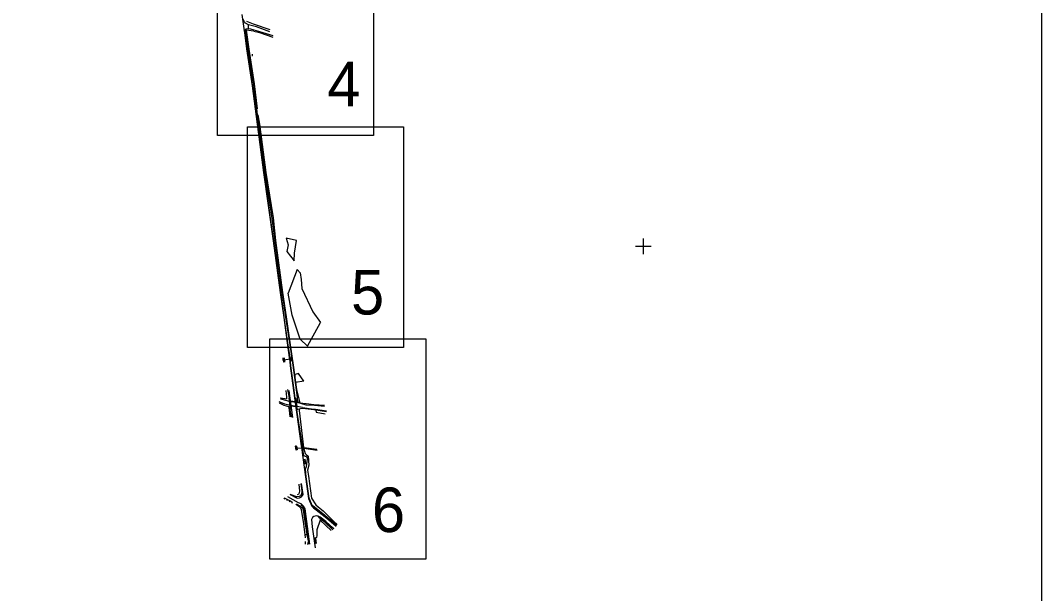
# Model space of a CAD drawing. Extents: x -866693 to -866303, y -1041966 to -1040244.
# Drawn here: x -866441.9 to -866373.2, y -1041273.4 to -1041234.8 of the extents above; entities that cross this region are included whole.
import ezdxf

# ---------------------------------------------------------------- set-up
doc = ezdxf.new("R2010")
doc.units = 0
for name, color, linetype in [('Formát', 7, 'Continuous'), ('Legenda', 7, 'Continuous'), ('Síť křížek', 7, 'Continuous')]:
    doc.layers.add(name, color=color, linetype=linetype)

msp = doc.modelspace()

# ---------------------------------------------------------------- linework, layer by layer
at = {"layer": 'Formát'}
msp.add_lwpolyline([(-866583.195, -1041098.65), (-866373.195, -1041098.65), (-866373.195, -1041395.65), (-866583.195, -1041395.65)], close=True, dxfattribs=at)
at = {"layer": 'Legenda'}
for p, q in [((-866426.854, -1041234.885), (-866426.936, -1041234.732)), ((-866426.787, -1041234.977), (-866426.854, -1041234.885)), ((-866426.587, -1041235.082), (-866426.787, -1041234.977)), ((-866426.248, -1041235.044), (-866426.69, -1041234.857)), ((-866426.59, -1041235.342), (-866426.587, -1041235.082)), ((-866426.042, -1041235.237), (-866426.587, -1041235.082)), ((-866425.13, -1041235.427), (-866426.248, -1041235.044)), ((-866425.153, -1041235.557), (-866426.042, -1041235.237)), ((-866426.866, -1041235.487), (-866426.844, -1041235.454)), ((-866426.844, -1041235.454), (-866426.731, -1041235.361)), ((-866426.844, -1041235.454), (-866426.742, -1041235.444)), ((-866426.806, -1041235.451), (-866426.844, -1041235.454)), ((-866426.682, -1041236.715), (-866426.844, -1041235.454)), ((-866426.742, -1041235.444), (-866426.806, -1041235.451)), ((-866426.806, -1041235.451), (-866426.618, -1041236.723)), ((-866426.225, -1041235.528), (-866426.742, -1041235.444)), ((-866426.742, -1041235.444), (-866426.553, -1041236.737)), ((-866426.731, -1041235.361), (-866426.59, -1041235.342)), ((-866426.59, -1041235.342), (-866426.458, -1041235.354)), ((-866426.458, -1041235.354), (-866425.836, -1041235.538)), ((-866426.225, -1041235.528), (-866425.839, -1041235.606)), ((-866425.839, -1041235.606), (-866424.946, -1041235.922)), ((-866425.836, -1041235.538), (-866424.939, -1041235.81)), ((-866426.312, -1041239.161), (-866426.682, -1041236.715)), ((-866426.618, -1041236.723), (-866426.257, -1041239.101)), ((-866426.553, -1041236.737), (-866426.204, -1041239.072)), ((-866426.074, -1041240.758), (-866426.312, -1041239.161)), ((-866426.257, -1041239.101), (-866426.05, -1041240.746)), ((-866426.204, -1041239.072), (-866425.999, -1041240.743)), ((-866426.074, -1041240.758), (-866425.999, -1041240.743)), ((-866426.05, -1041240.746), (-866426.074, -1041240.758)), ((-866425.999, -1041240.743), (-866426.05, -1041240.746)), ((-866426.05, -1041240.746), (-866425.997, -1041241.161)), ((-866426.052, -1041241.16), (-866425.951, -1041241.152)), ((-866425.973, -1041241.728), (-866426.052, -1041241.16)), ((-866425.997, -1041241.161), (-866426.052, -1041241.16)), ((-866425.951, -1041241.152), (-866425.997, -1041241.161)), ((-866425.997, -1041241.161), (-866425.904, -1041241.754)), ((-866425.951, -1041241.152), (-866425.849, -1041241.772)), ((-866425.515, -1041245.015), (-866425.973, -1041241.728)), ((-866425.904, -1041241.754), (-866425.468, -1041245.025)), ((-866425.849, -1041241.772), (-866425.42, -1041245.031)), ((-866425.093, -1041248.123), (-866425.515, -1041245.015)), ((-866425.468, -1041245.025), (-866425.018, -1041248.132)), ((-866425.42, -1041245.031), (-866424.93, -1041248.093)), ((-866424.889, -1041249.63), (-866425.093, -1041248.123)), ((-866425.018, -1041248.132), (-866424.81, -1041249.601)), ((-866424.93, -1041248.093), (-866424.766, -1041249.603)), ((-866424.393, -1041253.111), (-866424.889, -1041249.63)), ((-866424.81, -1041249.601), (-866424.32, -1041253.116)), ((-866424.766, -1041249.603), (-866424.286, -1041253.116)), ((-866423.346, -1041249.603), (-866424.053, -1041249.463)), ((-866424.053, -1041249.463), (-866423.912, -1041249.91)), ((-866423.497, -1041250.463), (-866423.346, -1041249.603)), ((-866423.912, -1041249.91), (-866424.01, -1041250.354)), ((-866424.01, -1041250.354), (-866423.506, -1041250.988)), ((-866423.506, -1041250.988), (-866423.497, -1041250.463)), ((-866423.314, -1041251.553), (-866423.921, -1041253.157)), ((-866423.314, -1041251.553), (-866423.115, -1041251.788)), ((-866423.115, -1041251.788), (-866423.045, -1041252.247)), ((-866423.045, -1041252.247), (-866422.989, -1041252.838)), ((-866424.177, -1041254.791), (-866424.393, -1041253.111)), ((-866424.32, -1041253.116), (-866424.086, -1041254.773)), ((-866424.286, -1041253.116), (-866424.058, -1041254.761)), ((-866423.652, -1041254.628), (-866423.921, -1041253.157)), ((-866422.989, -1041252.838), (-866422.264, -1041254.422)), ((-866422.264, -1041254.422), (-866421.741, -1041255.136)), ((-866423.941, -1041256.499), (-866424.177, -1041254.791)), ((-866424.086, -1041254.773), (-866423.818, -1041256.476)), ((-866424.058, -1041254.761), (-866423.793, -1041256.473)), ((-866423.109, -1041256.261), (-866423.652, -1041254.628)), ((-866422.605, -1041256.72), (-866421.741, -1041255.136)), ((-866423.78, -1041257.482), (-866423.941, -1041256.499)), ((-866423.818, -1041256.476), (-866423.597, -1041258.005)), ((-866423.793, -1041256.473), (-866423.576, -1041257.997)), ((-866422.605, -1041256.72), (-866423.109, -1041256.261)), ((-866424.245, -1041257.531), (-866424.27, -1041257.534)), ((-866424.269, -1041257.535), (-866424.27, -1041257.534)), ((-866424.27, -1041257.534), (-866424.262, -1041257.641)), ((-866424.249, -1041257.533), (-866424.269, -1041257.535)), ((-866424.269, -1041257.535), (-866424.235, -1041257.785)), ((-866424.262, -1041257.641), (-866424.26, -1041257.666)), ((-866423.737, -1041257.606), (-866424.26, -1041257.663)), ((-866424.26, -1041257.666), (-866424.255, -1041257.693)), ((-866424.255, -1041257.693), (-866424.237, -1041257.787)), ((-866424.249, -1041257.533), (-866424.245, -1041257.531)), ((-866424.214, -1041257.781), (-866424.249, -1041257.533)), ((-866424.245, -1041257.531), (-866424.208, -1041257.781)), ((-866424.208, -1041257.781), (-866424.237, -1041257.787)), ((-866424.237, -1041257.787), (-866424.235, -1041257.785)), ((-866424.235, -1041257.785), (-866424.214, -1041257.781)), ((-866424.208, -1041257.781), (-866424.214, -1041257.781)), ((-866424.128, -1041257.806), (-866424.169, -1041257.505)), ((-866423.78, -1041257.482), (-866423.757, -1041257.48)), ((-866423.78, -1041257.483), (-866423.757, -1041257.481)), ((-866423.78, -1041257.482), (-866423.78, -1041257.483)), ((-866423.748, -1041257.733), (-866423.78, -1041257.483)), ((-866423.757, -1041257.481), (-866423.757, -1041257.48)), ((-866423.746, -1041257.517), (-866423.757, -1041257.48)), ((-866423.757, -1041257.481), (-866423.726, -1041257.73)), ((-866423.726, -1041257.73), (-866423.748, -1041257.733)), ((-866423.748, -1041257.733), (-866423.746, -1041257.735)), ((-866423.74, -1041257.576), (-866423.746, -1041257.517)), ((-866423.746, -1041257.735), (-866423.725, -1041257.731)), ((-866423.724, -1041258.045), (-866423.746, -1041257.735)), ((-866423.734, -1041257.604), (-866423.74, -1041257.576)), ((-866423.732, -1041257.63), (-866423.734, -1041257.604)), ((-866423.725, -1041257.731), (-866423.732, -1041257.63)), ((-866423.725, -1041257.731), (-866423.726, -1041257.73)), ((-866423.506, -1041259.685), (-866423.724, -1041258.045)), ((-866423.597, -1041258.005), (-866423.384, -1041259.657)), ((-866423.576, -1041257.997), (-866423.351, -1041259.653)), ((-866423.215, -1041258.558), (-866423.447, -1041258.633)), ((-866423.416, -1041259.176), (-866423.447, -1041258.633)), ((-866422.856, -1041259.086), (-866423.215, -1041258.558)), ((-866422.856, -1041259.086), (-866423.416, -1041259.176)), ((-866424.076, -1041259.717), (-866424.031, -1041260.158)), ((-866423.96, -1041259.641), (-866423.856, -1041260.215)), ((-866423.434, -1041260.26), (-866423.506, -1041259.685)), ((-866423.384, -1041259.657), (-866423.314, -1041260.19)), ((-866423.351, -1041259.653), (-866423.128, -1041260.535)), ((-866424.149, -1041260.622), (-866424.529, -1041260.478)), ((-866424.514, -1041260.537), (-866424.208, -1041260.688)), ((-866424.443, -1041260.201), (-866424.139, -1041260.252)), ((-866424.44, -1041260.265), (-866424.014, -1041260.382)), ((-866424.208, -1041260.688), (-866423.898, -1041260.786)), ((-866423.789, -1041260.731), (-866424.149, -1041260.622)), ((-866424.139, -1041260.252), (-866424.032, -1041260.268)), ((-866424.031, -1041260.158), (-866424.032, -1041260.268)), ((-866424.014, -1041260.382), (-866423.871, -1041260.437)), ((-866423.871, -1041260.437), (-866423.362, -1041260.495)), ((-866423.821, -1041260.21), (-866423.856, -1041260.215)), ((-866423.828, -1041260.418), (-866423.856, -1041260.215)), ((-866423.856, -1041260.215), (-866423.855, -1041260.216)), ((-866423.855, -1041260.216), (-866423.821, -1041260.211)), ((-866423.855, -1041260.216), (-866423.83, -1041260.402)), ((-866423.831, -1041260.4), (-866423.796, -1041260.395)), ((-866423.83, -1041260.402), (-866423.831, -1041260.4)), ((-866423.828, -1041260.418), (-866423.831, -1041260.421)), ((-866423.784, -1041260.749), (-866423.831, -1041260.421)), ((-866423.367, -1041260.469), (-866423.831, -1041260.421)), ((-866423.83, -1041260.402), (-866423.796, -1041260.397)), ((-866423.795, -1041260.408), (-866423.83, -1041260.414)), ((-866423.782, -1041260.76), (-866423.83, -1041260.414)), ((-866423.83, -1041260.414), (-866423.829, -1041260.415)), ((-866423.829, -1041260.415), (-866423.794, -1041260.41)), ((-866423.78, -1041260.76), (-866423.829, -1041260.415)), ((-866423.821, -1041260.211), (-866423.821, -1041260.21)), ((-866423.821, -1041260.21), (-866423.796, -1041260.395)), ((-866423.821, -1041260.211), (-866423.796, -1041260.397)), ((-866423.796, -1041260.397), (-866423.796, -1041260.395)), ((-866423.747, -1041260.754), (-866423.795, -1041260.408)), ((-866423.793, -1041260.409), (-866423.794, -1041260.41)), ((-866423.746, -1041260.755), (-866423.794, -1041260.41)), ((-866423.322, -1041260.795), (-866423.789, -1041260.731)), ((-866423.433, -1041260.259), (-866423.434, -1041260.26)), ((-866423.409, -1041260.443), (-866423.434, -1041260.26)), ((-866423.4, -1041260.255), (-866423.433, -1041260.259)), ((-866423.408, -1041260.442), (-866423.433, -1041260.259)), ((-866423.375, -1041260.438), (-866423.409, -1041260.443)), ((-866423.408, -1041260.442), (-866423.409, -1041260.443)), ((-866423.406, -1041260.455), (-866423.409, -1041260.443)), ((-866423.374, -1041260.437), (-866423.408, -1041260.442)), ((-866423.371, -1041260.449), (-866423.406, -1041260.455)), ((-866423.406, -1041260.456), (-866423.371, -1041260.45)), ((-866423.406, -1041260.455), (-866423.406, -1041260.456)), ((-866423.406, -1041260.455), (-866423.359, -1041260.801)), ((-866423.406, -1041260.456), (-866423.358, -1041260.802)), ((-866423.374, -1041260.437), (-866423.4, -1041260.255)), ((-866423.4, -1041260.255), (-866423.396, -1041260.259)), ((-866423.396, -1041260.259), (-866423.375, -1041260.406)), ((-866423.284, -1041260.444), (-866423.375, -1041260.406)), ((-866423.375, -1041260.406), (-866423.367, -1041260.468)), ((-866423.374, -1041260.437), (-866423.375, -1041260.438)), ((-866423.375, -1041260.438), (-866423.371, -1041260.449)), ((-866423.371, -1041260.449), (-866423.371, -1041260.45)), ((-866423.323, -1041260.796), (-866423.371, -1041260.45)), ((-866423.367, -1041260.468), (-866423.362, -1041260.495)), ((-866423.367, -1041260.468), (-866423.367, -1041260.469)), ((-866423.367, -1041260.469), (-866423.326, -1041260.786)), ((-866422.709, -1041260.696), (-866423.362, -1041260.495)), ((-866423.314, -1041260.19), (-866423.284, -1041260.444)), ((-866423.284, -1041260.444), (-866423.128, -1041260.535)), ((-866423.128, -1041260.535), (-866422.707, -1041260.593)), ((-866422.145, -1041260.718), (-866422.709, -1041260.696)), ((-866422.707, -1041260.593), (-866422.182, -1041260.661)), ((-866422.182, -1041260.661), (-866421.477, -1041260.708)), ((-866421.465, -1041260.778), (-866422.145, -1041260.718)), ((-866423.898, -1041260.786), (-866423.854, -1041261.018)), ((-866423.854, -1041261.018), (-866423.804, -1041261.477)), ((-866423.784, -1041260.749), (-866423.326, -1041260.786)), ((-866423.784, -1041260.749), (-866423.783, -1041260.751)), ((-866423.754, -1041260.952), (-866423.783, -1041260.751)), ((-866423.782, -1041260.76), (-866423.747, -1041260.754)), ((-866423.78, -1041260.76), (-866423.782, -1041260.76)), ((-866423.78, -1041260.76), (-866423.746, -1041260.755)), ((-866423.778, -1041260.772), (-866423.744, -1041260.767)), ((-866423.754, -1041260.952), (-866423.778, -1041260.772)), ((-866423.777, -1041260.772), (-866423.778, -1041260.772)), ((-866423.777, -1041260.772), (-866423.743, -1041260.767)), ((-866423.776, -1041261.004), (-866423.754, -1041260.952)), ((-866423.69, -1041261.502), (-866423.776, -1041261.004)), ((-866423.717, -1041260.949), (-866423.754, -1041260.952)), ((-866423.754, -1041260.952), (-866423.718, -1041260.949)), ((-866423.754, -1041260.952), (-866423.754, -1041260.952)), ((-866423.747, -1041260.754), (-866423.746, -1041260.755)), ((-866423.744, -1041260.767), (-866423.717, -1041260.949)), ((-866423.743, -1041260.767), (-866423.744, -1041260.767)), ((-866423.743, -1041260.767), (-866423.718, -1041260.949)), ((-866423.718, -1041260.949), (-866423.717, -1041260.949)), ((-866423.359, -1041260.801), (-866423.324, -1041260.795)), ((-866423.359, -1041260.801), (-866423.358, -1041260.802)), ((-866423.357, -1041260.817), (-866423.359, -1041260.801)), ((-866423.358, -1041260.802), (-866423.323, -1041260.796)), ((-866423.357, -1041260.817), (-866423.322, -1041260.809)), ((-866423.357, -1041260.817), (-866423.356, -1041260.818)), ((-866423.357, -1041260.817), (-866423.332, -1041261.002)), ((-866423.356, -1041260.818), (-866423.321, -1041260.81)), ((-866423.333, -1041261.002), (-866423.356, -1041260.818)), ((-866423.333, -1041261.002), (-866423.298, -1041260.994)), ((-866423.332, -1041261.002), (-866423.333, -1041261.002)), ((-866423.291, -1041260.996), (-866423.332, -1041261.002)), ((-866423.269, -1041261.465), (-866423.332, -1041261.002)), ((-866423.326, -1041260.786), (-866423.322, -1041260.795)), ((-866423.324, -1041260.795), (-866423.323, -1041260.796)), ((-866423.322, -1041260.809), (-866423.324, -1041260.795)), ((-866422.959, -1041260.854), (-866423.322, -1041260.795)), ((-866423.291, -1041260.996), (-866423.322, -1041260.795)), ((-866423.322, -1041260.809), (-866423.321, -1041260.81)), ((-866423.298, -1041260.994), (-866423.321, -1041260.81)), ((-866423.298, -1041260.994), (-866423.291, -1041260.996)), ((-866423.175, -1041260.962), (-866423.291, -1041260.996)), ((-866423.079, -1041260.94), (-866423.175, -1041260.962)), ((-866423.175, -1041260.962), (-866423.164, -1041261.06)), ((-866423.164, -1041261.06), (-866422.887, -1041263.554)), ((-866422.958, -1041260.931), (-866423.079, -1041260.94)), ((-866422.959, -1041260.854), (-866422.175, -1041260.966)), ((-866422.182, -1041261.005), (-866422.958, -1041260.931)), ((-866421.333, -1041261.147), (-866422.182, -1041261.005)), ((-866422.175, -1041260.966), (-866422.066, -1041260.969)), ((-866422.066, -1041260.969), (-866421.323, -1041261.088)), ((-866422.066, -1041260.969), (-866422.027, -1041261.178)), ((-866422.027, -1041261.178), (-866421.424, -1041261.284)), ((-866422.954, -1041263.439), (-866423.269, -1041261.465)), ((-866423.435, -1041263.465), (-866423.41, -1041263.46)), ((-866423.435, -1041263.463), (-866423.41, -1041263.46)), ((-866423.435, -1041263.463), (-866423.435, -1041263.465)), ((-866423.435, -1041263.463), (-866423.43, -1041263.553)), ((-866423.435, -1041263.465), (-866423.401, -1041263.712)), ((-866423.349, -1041263.451), (-866423.41, -1041263.46)), ((-866423.41, -1041263.46), (-866423.41, -1041263.46)), ((-866423.41, -1041263.46), (-866423.375, -1041263.707)), ((-866423.349, -1041263.451), (-866423.314, -1041263.712)), ((-866423.028, -1041263.445), (-866422.954, -1041263.439)), ((-866422.954, -1041263.439), (-866422.923, -1041263.435)), ((-866422.954, -1041263.439), (-866422.928, -1041263.435)), ((-866422.919, -1041263.688), (-866422.954, -1041263.439)), ((-866422.954, -1041263.439), (-866422.954, -1041263.439)), ((-866422.923, -1041263.435), (-866422.928, -1041263.435)), ((-866422.928, -1041263.435), (-866422.907, -1041263.536)), ((-866422.892, -1041263.684), (-866422.923, -1041263.435)), ((-866423.43, -1041263.553), (-866423.427, -1041263.58)), ((-866423.427, -1041263.58), (-866423.422, -1041263.606)), ((-866423.426, -1041263.583), (-866422.906, -1041263.562)), ((-866423.422, -1041263.606), (-866423.401, -1041263.714)), ((-866423.401, -1041263.712), (-866423.375, -1041263.707)), ((-866423.373, -1041263.707), (-866423.401, -1041263.714)), ((-866423.401, -1041263.714), (-866423.401, -1041263.712)), ((-866423.375, -1041263.707), (-866423.373, -1041263.707)), ((-866423.314, -1041263.712), (-866423.373, -1041263.707)), ((-866422.992, -1041263.709), (-866422.918, -1041263.688)), ((-866422.919, -1041263.688), (-866422.892, -1041263.684)), ((-866422.918, -1041263.688), (-866422.919, -1041263.688)), ((-866422.891, -1041263.684), (-866422.918, -1041263.688)), ((-866422.868, -1041264.102), (-866422.918, -1041263.688)), ((-866422.907, -1041263.536), (-866422.904, -1041263.554)), ((-866422.904, -1041263.554), (-866422.9, -1041263.578)), ((-866422.904, -1041263.554), (-866422.887, -1041263.554)), ((-866422.9, -1041263.578), (-866422.891, -1041263.684)), ((-866422.892, -1041263.684), (-866422.891, -1041263.684)), ((-866422.887, -1041263.554), (-866422.778, -1041263.945)), ((-866422.887, -1041263.554), (-866421.96, -1041263.704)), ((-866422.869, -1041263.542), (-866421.973, -1041263.666)), ((-866422.792, -1041264.124), (-866422.868, -1041264.102)), ((-866422.862, -1041263.584), (-866421.951, -1041263.729)), ((-866422.638, -1041264.195), (-866422.792, -1041264.124)), ((-866422.778, -1041263.945), (-866422.701, -1041264.013)), ((-866422.701, -1041264.013), (-866422.561, -1041264.137)), ((-866422.561, -1041264.137), (-866422.524, -1041264.728)), ((-866422.848, -1041264.353), (-866422.761, -1041264.341)), ((-866422.812, -1041264.646), (-866422.848, -1041264.353)), ((-866422.812, -1041264.646), (-866422.726, -1041264.634)), ((-866422.726, -1041264.634), (-866422.761, -1041264.341)), ((-866422.741, -1041264.986), (-866422.68, -1041264.821)), ((-866422.68, -1041264.821), (-866422.605, -1041264.324)), ((-866422.605, -1041264.324), (-866422.638, -1041264.195)), ((-866422.524, -1041264.728), (-866422.602, -1041265.066)), ((-866422.702, -1041265.527), (-866422.741, -1041264.986)), ((-866422.495, -1041266.968), (-866422.702, -1041265.527)), ((-866422.602, -1041265.066), (-866422.54, -1041265.474)), ((-866422.54, -1041265.474), (-866422.34, -1041266.964)), ((-866423.127, -1041266.491), (-866423.174, -1041266.022)), ((-866423.05, -1041265.989), (-866422.988, -1041266.476)), ((-866423.333, -1041266.863), (-866423.78, -1041266.723)), ((-866423.173, -1041266.856), (-866423.333, -1041266.863)), ((-866423.28, -1041266.72), (-866423.163, -1041266.658)), ((-866423.093, -1041266.796), (-866423.173, -1041266.856)), ((-866423.163, -1041266.658), (-866423.127, -1041266.491)), ((-866423.007, -1041266.679), (-866423.093, -1041266.796)), ((-866422.988, -1041266.476), (-866423.007, -1041266.679)), ((-866424.157, -1041266.952), (-866424.197, -1041267.023)), ((-866423.979, -1041267.052), (-866424.157, -1041266.952)), ((-866423.979, -1041267.052), (-866424.018, -1041267.122)), ((-866423.812, -1041267.145), (-866423.979, -1041267.052)), ((-866423.812, -1041267.145), (-866423.854, -1041267.218)), ((-866423.634, -1041267.249), (-866423.812, -1041267.145)), ((-866423.634, -1041267.249), (-866423.676, -1041267.321)), ((-866423.122, -1041267.556), (-866423.404, -1041267.383)), ((-866423.342, -1041267.384), (-866423.325, -1041267.359)), ((-866423.342, -1041267.384), (-866423.32, -1041267.399)), ((-866423.325, -1041267.359), (-866423.304, -1041267.374)), ((-866423.32, -1041267.399), (-866423.304, -1041267.374)), ((-866423.312, -1041267.374), (-866423.047, -1041267.547)), ((-866423.013, -1041267.749), (-866423.083, -1041267.582)), ((-866422.908, -1041267.532), (-866423.072, -1041267.417)), ((-866423.047, -1041267.547), (-866422.947, -1041267.622)), ((-866422.846, -1041267.663), (-866422.908, -1041267.532)), ((-866422.298, -1041267.443), (-866422.495, -1041266.968)), ((-866422.34, -1041266.964), (-866422.057, -1041267.407)), ((-866422.162, -1041267.549), (-866422.298, -1041267.443)), ((-866421.998, -1041267.673), (-866422.162, -1041267.549)), ((-866422.057, -1041267.407), (-866421.899, -1041267.548)), ((-866421.899, -1041267.548), (-866421.548, -1041267.823)), ((-866422.881, -1041268.535), (-866423.013, -1041267.749)), ((-866422.947, -1041267.622), (-866422.901, -1041267.753)), ((-866422.901, -1041267.753), (-866422.795, -1041268.535)), ((-866422.817, -1041267.78), (-866422.846, -1041267.663)), ((-866422.695, -1041268.544), (-866422.817, -1041267.78)), ((-866421.576, -1041268.004), (-866421.998, -1041267.673)), ((-866421.773, -1041268.297), (-866421.893, -1041268.173)), ((-866421.153, -1041268.366), (-866421.576, -1041268.004)), ((-866421.548, -1041267.823), (-866420.848, -1041268.539)), ((-866422.755, -1041269.601), (-866422.881, -1041268.535)), ((-866422.795, -1041268.535), (-866422.657, -1041269.405)), ((-866422.598, -1041269.211), (-866422.695, -1041268.544)), ((-866421.77, -1041268.451), (-866421.985, -1041269.087)), ((-866421.45, -1041268.579), (-866421.789, -1041268.358)), ((-866421.419, -1041268.563), (-866421.773, -1041268.297)), ((-866421.018, -1041269.133), (-866421.77, -1041268.451)), ((-866420.916, -1041269.088), (-866421.45, -1041268.579)), ((-866420.836, -1041269.025), (-866421.419, -1041268.563)), ((-866420.64, -1041268.788), (-866421.153, -1041268.366)), ((-866420.848, -1041268.539), (-866420.616, -1041268.741)), ((-866422.756, -1041269.623), (-866422.755, -1041269.601)), ((-866422.583, -1041269.424), (-866422.72, -1041269.432)), ((-866422.657, -1041269.405), (-866422.538, -1041269.941)), ((-866422.583, -1041269.424), (-866422.598, -1041269.211)), ((-866422.017, -1041269.612), (-866422.121, -1041269.662)), ((-866422.086, -1041270.023), (-866422.121, -1041269.662)), ((-866422.071, -1041269.659), (-866422.038, -1041270.016)), ((-866421.99, -1041269.471), (-866422.017, -1041269.612)), ((-866421.985, -1041269.087), (-866421.99, -1041269.471)), ((-866422.746, -1041270.058), (-866422.744, -1041269.879)), ((-866422.579, -1041270.077), (-866422.559, -1041269.971)), ((-866422.559, -1041269.971), (-866422.557, -1041269.935)), ((-866422.545, -1041269.97), (-866422.559, -1041269.971)), ((-866422.559, -1041269.971), (-866422.545, -1041269.982)), ((-866422.557, -1041269.935), (-866422.502, -1041269.931)), ((-866422.545, -1041269.97), (-866422.543, -1041269.94)), ((-866422.545, -1041269.982), (-866422.543, -1041269.941)), ((-866422.545, -1041269.982), (-866422.545, -1041269.97)), ((-866422.543, -1041269.94), (-866422.526, -1041269.938)), ((-866422.543, -1041269.941), (-866422.538, -1041269.941)), ((-866422.538, -1041269.941), (-866422.527, -1041269.938)), ((-866422.524, -1041270.065), (-866422.538, -1041269.941)), ((-866422.527, -1041269.938), (-866422.518, -1041269.976)), ((-866422.526, -1041269.938), (-866422.517, -1041269.976)), ((-866422.518, -1041269.976), (-866422.517, -1041269.976)), ((-866422.503, -1041269.958), (-866422.517, -1041269.976)), ((-866422.479, -1041270.055), (-866422.517, -1041269.976)), ((-866422.502, -1041269.931), (-866422.503, -1041269.958))]:
    msp.add_line(p, q, dxfattribs=at)
for points in [[(-866428.667, -1041227.702), (-866418.167, -1041227.702), (-866418.167, -1041242.552), (-866428.667, -1041242.552)], [(-866426.658, -1041241.967), (-866416.158, -1041241.967), (-866416.158, -1041256.817), (-866426.658, -1041256.817)], [(-866425.151, -1041256.226), (-866414.651, -1041256.226), (-866414.651, -1041271.076), (-866425.151, -1041271.076)]]:
    msp.add_lwpolyline(points, close=True, dxfattribs=at)
for points in [[(-866427.025, -1041234.389), (-866426.866, -1041235.487), (-866426.858, -1041235.608), (-866426.708, -1041236.708), (-866426.347, -1041239.201), (-866425.997, -1041241.783), (-866425.564, -1041245.023), (-866424.927, -1041249.642), (-866424.446, -1041253.104), (-866424.213, -1041254.799), (-866423.978, -1041256.503), (-866423.844, -1041257.483), (-866423.811, -1041257.757), (-866423.771, -1041258.052), (-866423.546, -1041259.702), (-866423.028, -1041263.445), (-866422.992, -1041263.709), (-866422.924, -1041264.218), (-866422.748, -1041265.53), (-866422.551, -1041266.971), (-866422.313, -1041267.509), (-866422.21, -1041267.602), (-866422.035, -1041267.752), (-866421.62, -1041268.067), (-866421.184, -1041268.421), (-866420.675, -1041268.837)], [(-866426.369, -1041237.148), (-866426.319, -1041237.148)], [(-866426.344, -1041237.073), (-866426.344, -1041237.148)], [(-866423.604, -1041261.524), (-866423.811, -1041260.061), (-866423.842, -1041259.707)], [(-866423.78, -1041266.723), (-866423.301, -1041266.951), (-866423.151, -1041266.94), (-866423.017, -1041266.859), (-866422.912, -1041266.704), (-866423.011, -1041265.972)], [(-866422.446, -1041270.054), (-866422.658, -1041268.539), (-866422.773, -1041267.688), (-866422.873, -1041267.506), (-866423.031, -1041267.345), (-866423.209, -1041267.263), (-866423.936, -1041266.859)], [(-866420.836, -1041269.025), (-866421.379, -1041268.528), (-866421.766, -1041268.242), (-866421.893, -1041268.173), (-866422.008, -1041268.146), (-866422.195, -1041268.186), (-866422.268, -1041268.262), (-866422.344, -1041268.389), (-866422.289, -1041268.893), (-866422.092, -1041270.295)]]:
    msp.add_lwpolyline(points, dxfattribs=at)
at = {"layer": 'Síť křížek'}
for p, q in [((-866400, -1041250.53), (-866400, -1041249.47)), ((-866400.53, -1041250), (-866399.47, -1041250))]:
    msp.add_line(p, q, dxfattribs=at)

# ---------------------------------------------------------------- texts
at = {"layer": 'Formát'}
for s, p in [('4', (-866421.271, -1041240.579)), ('5', (-866419.681, -1041254.594)), ('6', (-866418.273, -1041269.242))]:
    msp.add_text(s, height=3, dxfattribs=at).set_placement(p)

doc.saveas('drawing.dxf')
